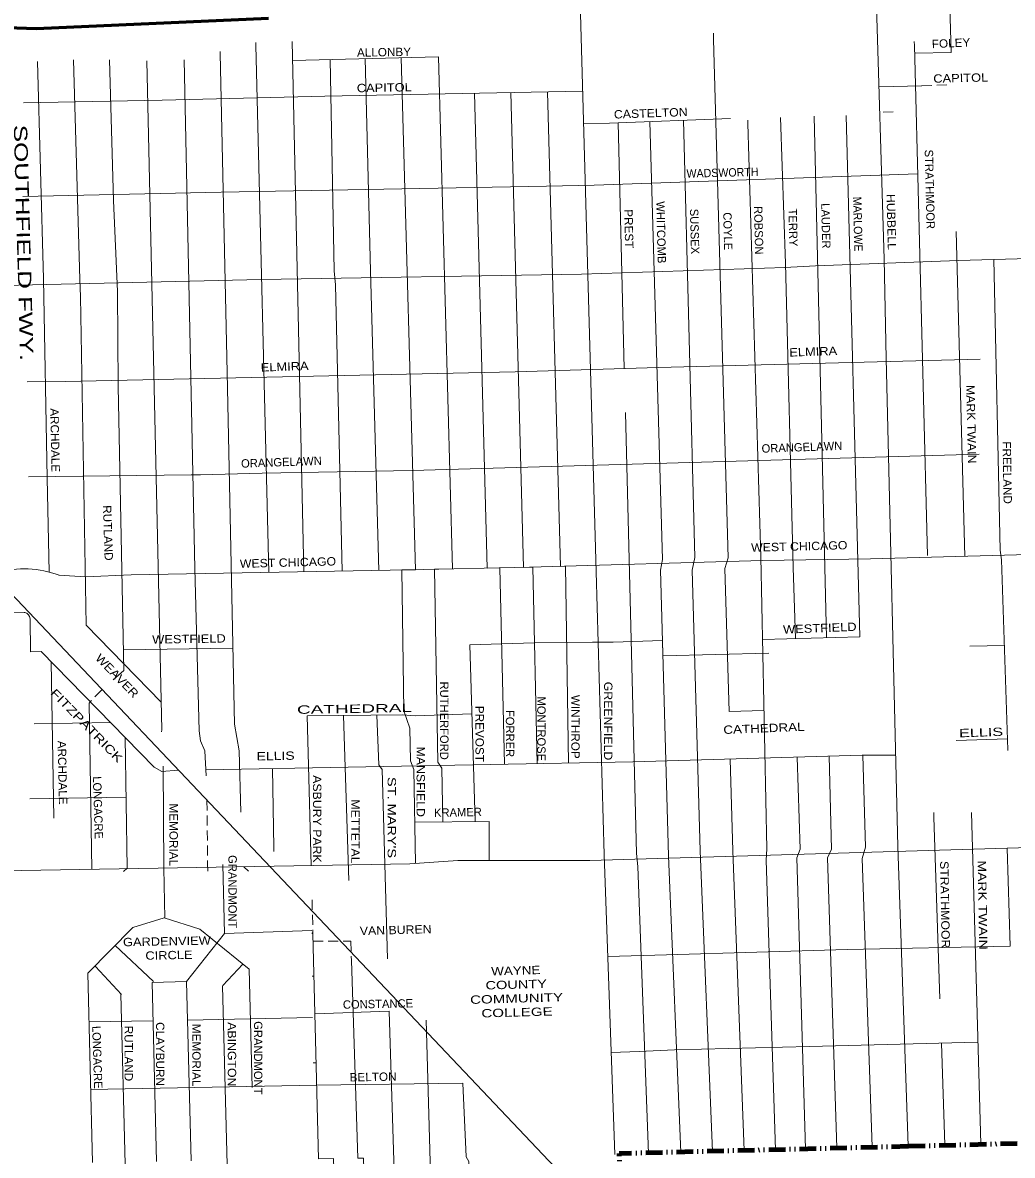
# Model space of a CAD drawing. Extents: x 34705 to 138605, y 34275 to 143551.
# Drawn here: x 54154 to 63036, y 107069 to 117233 of the extents above; entities that cross this region are included whole.
import ezdxf
from ezdxf.enums import TextEntityAlignment as Align

# ---------------------------------------------------------------- set-up
doc = ezdxf.new("R2010")
doc.units = 0
doc.header["$LTSCALE"] = 30
doc.linetypes.add('DASH_DOUBLE_DOT', pattern=[9.2, 5, -1.2, 0.3, -1.2, 0.3, -1.2])
doc.linetypes.add('MEDIUM_DASHED', pattern=[4.5, 3, -1.5])
for name, color, linetype, lineweight in [('1', 7, 'Continuous', 13), ('11', 7, 'Continuous', 13), ('50', 7, 'Continuous', 13), ('51', 7, 'Continuous', 35), ('59', 7, 'DASH_DOUBLE_DOT', 106)]:
    doc.layers.add(name, color=color, linetype=linetype, lineweight=lineweight)

msp = doc.modelspace()

# ---------------------------------------------------------------- linework, layer by layer
at = {"layer": '1'}
for p, q in [((56571.12, 117064.72), (56678.04, 112305.29)), ((56574.95, 116894.51), (57885.23, 116925.82)), ((62159.2, 116960.26), (62486.23, 116964.8)), ((61839.17, 116656.14), (62221.01, 116667.06)), ((61257.31, 116394.83), (61367.08, 111713.13)), ((61544.82, 116401.03), (61667.13, 111721.32)), ((59497.55, 116333.43), (59553.16, 114128.11)), ((62531.88, 115360.4), (62608.33, 112441.56)), ((54219.61, 111884.54), (54223.08, 111586.9)), ((54723.7, 111825.17), (55396.56, 111135.87)), ((60793.32, 111697.48), (61667.13, 111721.32)), ((55057.41, 111605.74), (56039.65, 111621.22)), ((58167.28, 111651.19), (58216, 110063.17)), ((62653.95, 111636.51), (62964.87, 111644.49)), ((54410.01, 111496.33), (54432.83, 110095.19)), ((56707.13, 111013.72), (56742.82, 109668.54)), ((57033.71, 111016.67), (57080.65, 109536.08)), ((60493.36, 111051.96), (60806.77, 111060.21)), ((54257.41, 110941.34), (54943.75, 110952.62)), ((62530.97, 110790.77), (62992.76, 110806.7)), ((55414.35, 110559.67), (55419.78, 109646.04)), ((54217.06, 110268.58), (55082.01, 110283.75)), ((62668.48, 110145.25), (62752.45, 107173.38)), ((62990.46, 109823.82), (63016.12, 108946.83)), ((55419.78, 109646.04), (55430.79, 109197.62)), ((56139.63, 109658.28), (56179.96, 109620.23)), ((56748.25, 109066.01), (56758.48, 109054.95)), ((55625.31, 108628.52), (55966.16, 109059.65)), ((54982.97, 108951.23), (55326.76, 108628.52)), ((55041.15, 108511.98), (54806.4, 108764.37)), ((55950.51, 108591.62), (56129.68, 108785.34)), ((54738.37, 108703.06), (54780.11, 107003.63)), ((56186.99, 108738.64), (56213.07, 107676.57)), ((56752.67, 108676.4), (56767.76, 108676.9)), ((55314.79, 108620.9), (55625.31, 108628.52)), ((55314.79, 108620.9), (55354.27, 107013.34)), ((55625.31, 108628.52), (55664.85, 107018.6)), ((55948.62, 108589.57), (55988.06, 106983.62)), ((55035.71, 108514.29), (55073.16, 106989.62)), ((56776.09, 108337.51), (57442.56, 108361.32)), ((55323.23, 108276.96), (54749.11, 108265.68)), ((56754.28, 108305.07), (55633.79, 108283.06)), ((62399.37, 108076.46), (62429.56, 107163.12)), ((56761.51, 107898.92), (56786.85, 107898.92)), ((56791.74, 107699.78), (54763.91, 107659.95)), ((56791.74, 107699.78), (58104.66, 107715.6))]:
    msp.add_line(p, q, dxfattribs=at)
at = {"layer": '1', "linetype": 'MEDIUM_DASHED'}
for p, q in [((62223.51, 116667.13), (62449.23, 116673.58)), ((61876.25, 116428.56), (62002.29, 116433.23)), ((54863.92, 111247.18), (54760.58, 111138.57)), ((55807.35, 110253.12), (55813.82, 109652.74)), ((56750.95, 109361.84), (56758.48, 109055.1)), ((56760.04, 108991.66), (57097.93, 108991.66)), ((57097.93, 108991.66), (57103.55, 108817.23))]:
    msp.add_line(p, q, dxfattribs=at)
at = {"layer": '1'}
for points in [[(61799.97, 117893.3), (61810.66, 117579.32), (61886.86, 115111.82), (61904.86, 114220.52), (62009.46, 109840.12), (62100.56, 107154.18)], [(59156.14, 117419.97), (59299.97, 112306.17), (59371.51, 109768.6), (59467.9, 107076.6)], [(62469.74, 117407.16), (62474.36, 117381.92), (62486.23, 116964.8)], [(60353.03, 117137.36), (60354.23, 117080.61), (60484.66, 112430.42), (60454.76, 112334.62), (60493.36, 111051.96)], [(56246.14, 117054.36), (56246.96, 117032.18), (56363.82, 112299.47)], [(62153.89, 117064.56), (62157.46, 117029.02), (62273.03, 112452.52)], [(54610.21, 116897.96), (54666.34, 114928.14), (54671.96, 114776.22), (54723.7, 111825.17)], [(54934.03, 116899.27), (54970.07, 115635.68), (55003.82, 114819.84), (55009.44, 113970.24), (55061.16, 111420.92), (54965.56, 111337.12)], [(55602.17, 116899.09), (55698.47, 112335.75), (55737.84, 110878.49), (55748.86, 110789.82), (55788.46, 110698.44), (55799.71, 110473.38)], [(55925.96, 116973.09), (55926.76, 116957.22), (55988.13, 114094.02), (56053.86, 110939.32), (56095.66, 110700.02), (56112.01, 110148.89)], [(56912.74, 116902.58), (56949.95, 115006.91), (56961.26, 114881.52), (57022.26, 112311.67)], [(57228.43, 116910.12), (57276.18, 115006.91), (57351.47, 112317.77)], [(57550.14, 116917.81), (57678.31, 112323.99), (57555.44, 112321.55), (57575.66, 111059.02), (57629.46, 110903.42), (57635.46, 110610.32), (57665.36, 110532.52), (57680.06, 109687.26)], [(57885.23, 116925.82), (58012.13, 112331.09), (57849.82, 112327.64), (57880.56, 110598.32), (57916.46, 110544.52), (57925.88, 110060.6)], [(54285.96, 116885.59), (54340.11, 114933.77), (54373.56, 113146.72), (54390.97, 112303.04)], [(55268.67, 116889.83), (55402.06, 110888.52), (55400.61, 110869.71)], [(54160.99, 116513.49), (55404.58, 116538.88), (56864.11, 116573.64), (59180.33, 116617.67)], [(58208.68, 116599.2), (58321.61, 112337.68), (58436.71, 112340.13), (58477.37, 110577.69)], [(58535.01, 116605.4), (58649.32, 112344.65), (58731.14, 112346.63), (58770.49, 110583)], [(58863.83, 116611.65), (58980.39, 112353.96), (59024.39, 112355.25), (59051.37, 110588.09)], [(60955.56, 116382.92), (61001.1, 115071.62), (61068.6, 112342.78), (61088.69, 111705.53)], [(59189.13, 116325.6), (59419.39, 116330.3), (60505.35, 116373.76)], [(59781.66, 116344.8), (59895.66, 112415.42), (59877.76, 112319.72), (59949.56, 109757.82), (60061.8, 107094.1)], [(60085.12, 116356.94), (60185.66, 112433.42), (60161.76, 112319.72), (60235.06, 109801.22), (60343.66, 107102.41)], [(60662.69, 116359.02), (60662.56, 116329.12), (60777.66, 112439.32), (60832.96, 109819.22), (60827.06, 109717.52), (60910.83, 107119.12)], [(54153.92, 115673.69), (55934.44, 115713.34), (58855.13, 115767.16), (59284.18, 115774.93), (62186.58, 115875.92)], [(40613.4, 114632.16), (42489.2, 114668.24), (47370.61, 114750.8), (48708.52, 114746.45), (48856.21, 114755.14), (56295.69, 114929.11), (59170.26, 114975.24), (60993.76, 115036.75), (61270.46, 115052.13), (62554.03, 115098.26), (64448.63, 115152.08), (64617.72, 115144.39), (66562.29, 115190.52), (67177.17, 115213.59), (67584.53, 115228.96), (71855.3, 115368.15)], [(62869.23, 115107.21), (62927.36, 112497.82), (62939.26, 112414.02), (62996.06, 110707.52), (62996.02, 110701.52)], [(54193.27, 114008.47), (54535.58, 114014.17), (58572.66, 114098.75), (59856.23, 114137.19), (62746.18, 114214.08)], [(59563.09, 113734.35), (59662.46, 109775.82), (59674.46, 109662.12), (59769.76, 107085.5)], [(54206.39, 113155.96), (55665.43, 113176.13), (55749.98, 113176.13), (56303.37, 113191.5), (57648.43, 113214.57), (62738.49, 113360.65)], [(54478.94, 112274.29), (54716.56, 112260.76), (55127.41, 112276.57), (57617.68, 112322.7), (58701.41, 112345.76), (60793.93, 112407.27), (61762.37, 112422.65), (68207.1, 112599.49), (70854.93, 112668.68), (71769.57, 112676.37), (72161.56, 112699.44), (75134.56, 112784.19)], [(53834.93, 111923.31), (53892.56, 111935.02), (54172.09, 111939.12)], [(58167.28, 111651.19), (58745.61, 111667.26), (59268.26, 111674.95), (59452.72, 111674.95), (59895.43, 111689.19), (59899.28, 111551.75), (60851.58, 111575)], [(54223.08, 111586.9), (54319.46, 111588.73), (55334.93, 110552.43), (55404.11, 110513.98), (55548.36, 110526.01)], [(54760.58, 111138.57), (54750.26, 111127.72), (54774.53, 109635.01)], [(56707.13, 111013.72), (57561.96, 111021.43), (57677.25, 111013.74), (58186.35, 111029.65)], [(57333.37, 111019.37), (57351.36, 110574.42), (57381.26, 110532.52), (57429.15, 108833.47)], [(55074.41, 110818.95), (55091.06, 109645.72), (55059.18, 109616.27)], [(55796.92, 110529.13), (59629.5, 110598.56), (61689.36, 110660.07), (61989.87, 110660.48)], [(60504.57, 110624.69), (60528.06, 109801.22), (60630.28, 107110.85)], [(61105.45, 110642.63), (61130.46, 109816.22), (61100.56, 109738.42), (61180.23, 107127.06)], [(61391.98, 110651.19), (61411.56, 109816.22), (61375.66, 109738.42), (61461.18, 107135.34)], [(61694.87, 110660.07), (61716.46, 109834.12), (61686.56, 109732.42), (61777.56, 107144.66)], [(56394.61, 110539.96), (56406.56, 109831.12), (56409.19, 109796.15)], [(62331.3, 110145.35), (62332.36, 110103.32), (62386.23, 108473.77)], [(40755.85, 109370.6), (41156.14, 109376.08), (42170.69, 109391.46), (42339.79, 109406.84), (42555, 109452.97), (42654.91, 109483.72), (42808.63, 109506.79), (42946.98, 109514.48), (43077.65, 109499.1), (43215.99, 109468.34), (43369.71, 109422.21), (43531.12, 109414.52), (43700.21, 109422.21), (48173.49, 109522.16), (55369.51, 109645.18), (57629.21, 109683.62), (58059.62, 109714.38), (59243.27, 109714.38), (63191.97, 109829.71), (66639.15, 109914.28), (68637.52, 109960.41), (71243.21, 110034.61)], [(57673.6, 110058.37), (58340.9, 110064.28), (58340.61, 109714.38)], [(55950.94, 109679.65), (55966.16, 109059.65), (56749.37, 109087.63)], [(55814.42, 109652.75), (55814.66, 109632.22), (55814.66, 109618.94)], [(54738.37, 108703.06), (55142.6, 109113.61), (55424.7, 109199.53), (55744.8, 109098.97), (56186.99, 108738.64)], [(56758.49, 109054.95), (56808.02, 107037.96), (56944.05, 107040.26), (57029.13, 104394.12), (56883.31, 104391.5), (56950.86, 101784.23)], [(59404.3, 108852.85), (59933.09, 108868.64), (61554.84, 108914.77), (63016.12, 108946.83)], [(57103.55, 108817.23), (57160.72, 107043.93), (57212.55, 107044.8), (57293.42, 104398.87), (57236.89, 104397.85), (57309.89, 101788.29)], [(57442.56, 108361.32), (57608.46, 103092.22), (57638.41, 101792)], [(57775.96, 108281.72), (57835.76, 106162.62), (57900.52, 104474.17), (57937.36, 103110.22), (57973.38, 101795.79)], [(59435.12, 107991.96), (59687.14, 107999.83), (60002.27, 108015.21), (61216.66, 108045.97), (62726.7, 108084.9)], [(58104.66, 107715.6), (58134.66, 107055.42), (58158.66, 107013.52), (58314.79, 101799.65)]]:
    msp.add_lwpolyline(points, dxfattribs=at)
for centre, radius, start, end in [((54168.04, 111463.65), 868.49, 68.96068, 106.22392), ((54172.01, 111888.66), 50.46, 89.91597, 94.47871), ((54162.51, 111882.8), 57.12, 1.75211, 80.35073)]:
    msp.add_arc(centre, radius, start, end, dxfattribs=at)
at = {"layer": '50'}
msp.add_line((59512.68, 106348.96), (49626.02, 116766.15), dxfattribs=at)
at = {"layer": '51', "lineweight": 60}
msp.add_lwpolyline([(48854.63, 117669.11), (49514.91, 117195.42), (49843.37, 117046.99), (50290.23, 116966.93), (50990.53, 116953.58), (51340.96, 116954.17), (52322.56, 117053.7), (53651.68, 117200.44), (54278.61, 117180.42), (56361.16, 117273.82)], dxfattribs=at)
at = {"layer": '59'}
for p, q in [((62102.57, 107149.74), (59507.74, 107085.4)), ((62102.47, 107149.64), (64732.95, 107219.29))]:
    msp.add_line(p, q, dxfattribs=at)
msp.add_lwpolyline([(56980.51, 101772.19), (56980.51, 101772.19), (59657.77, 101818.91), (59507.74, 107085.4)], dxfattribs=at)

# ---------------------------------------------------------------- texts
at = {"layer": '11'}
for s, height, rotation, width, p in [('FOLEY', 75, 2.748, 1.05, (62487.37, 117011.83)), ('ALLONBY', 75, 0.879, 1.05, (57397.06, 116930.99)), ('CAPITOL', 75, 1.071, 1.15, (57399.72, 116612.85)), ('CAPITOL', 75, 1.373, 1.15, (62573.91, 116699.25)), ('CASTELTON', 75, 2, 1.1, (59791.83, 116383.53)), ('SOUTHFIELD FWY.', 120, 271.584, 1.45, (54102.7, 115255.21)), ('WADSWORTH', 75, 1.389, 0.95, (60435.15, 115849.71)), ('HUBBELL', 75, 271.388, 1.1, (61912.81, 115443.81)), ('MARLOWE', 75, 271.391, 0.95, (61611.93, 115424.41)), ('PREST', 75, 271.39, 1.05, (59556.85, 115382.04)), ('ELMIRA', 75, 2.069, 1.15, (61249.93, 114243.72)), ('ELMIRA', 75, 2.069, 1.15, (56506.19, 114109.32)), ('MARK TWAIN', 75, 271.372, 1.1, (62629.92, 113628.83)), ('ARCHDALE', 75, 271.201, 1.05, (54406.88, 113485.44)), ('FREELAND', 75, 271.002, 1.05, (62952.74, 113194.81)), ('RUTLAND', 75, 271.854, 1.05, (54881.75, 112653.12)), ('WEST CHICAGO', 75, 1.498, 1.1, (61124.29, 112496.18)), ('WEST CHICAGO', 75, 1.498, 1.1, (56535.57, 112351.44)), ('WESTFIELD', 75, 2.267, 1.15, (61309.31, 111762.55)), ('WESTFIELD', 75, 0.945, 1.15, (55646.91, 111665.4)), ('WEAVER', 75, 314.272, 1.15, (54974.23, 111345.57)), ('GREENFIELD', 75, 270, 1.1, (59371.63, 110966.06)), ('FITZPATRICK', 75, 314.299, 1.35, (54702.1, 110899.44)), ('WINTHROP', 75, 270, 1.05, (59077.81, 110914.25)), ('CATHEDRAL', 75, 0.975, 1.7, (57132.62, 111038.97)), ('PREVOST', 75, 270, 1.05, (58217.76, 110850.63)), ('CATHEDRAL ', 75, 2.268, 1.2, (60824.46, 110864.4)), ('ELLIS   ', 75, 2.001, 1.45, (62816.73, 110828.56)), ('ARCHDALE', 75, 271.201, 1.05, (54473.42, 110502.1)), ('ELLIS', 75, 1.211, 1.25, (56424.8, 110615.2)), ('MANSFIELD', 75, 270, 1.1, (57688.9, 110420.99)), ('ASBURY PARK', 75, 270, 1.1, (56759.39, 110087.54)), ("ST. MARY'S", 75, 270, 1.3, (57429.28, 110100.36)), ('MEMORIAL', 75, 270, 1.05, (55471.39, 109945.21)), ('METTETAL', 75, 270, 1.1, (57102.35, 109975.32)), ('STRATHMOOR ', 75, 271, 1.1, (62394.64, 109301.71)), ('MARK TWAIN ', 75, 271.001, 1.25, (62731.82, 109296.46)), ('VAN BUREN', 75, 1.58, 1.1, (57502.5, 109053.59)), ('GARDENVIEW ', 75, 1.14, 1.15, (55464.86, 108952.54)), ('CIRCLE', 75, 1.14, 1.15, (55467.35, 108827.56)), ('WAYNE', 75, 1.665, 1.2, (58580.42, 108689.24)), ('COUNTY', 75, 1.665, 1.3, (58584.05, 108564.29)), ('COMMUNITY', 75, 1.665, 1.35, (58587.68, 108439.34)), ('COLLEGE', 75, 1.665, 1.35, (58591.31, 108314.4)), ('CLAYBURN', 75, 270, 1.05, (55350.39, 107977.71)), ('ABINGTON', 75, 270, 1.1, (55994.82, 107975.22)), ('RUTLAND', 75, 270, 1.05, (55068.08, 107982.83)), ('MEMORIAL', 75, 270, 1.05, (55676.2, 107967.9)), ('BELTON', 75, 1.056, 1.05, (57299.1, 107735.21))]:
    msp.add_text(s, height=height, rotation=rotation, dxfattribs=dict(at, width=width)).set_placement(p, align=Align.CENTER)
for s, rotation, p in [('STRATHMOOR', 271.372, (62257.46, 115736.51)), ('WHITCOMB', 271.39, (59846.43, 115350.37)), ('ROBSON', 271.389, (60722.32, 115369.38)), ('LAUDER', 271.39, (61324.69, 115408.68)), ('SUSSEX', 271.39, (60147.26, 115358.69)), ('COYLE', 271.386, (60445, 115360.53)), ('TERRY', 271.39, (61030.48, 115393.7)), ('ORANGELAWN', 2.069, (61148.6, 113386.55)), ('ORANGELAWN', 2.069, (56477.21, 113252.15)), ('RUTHERFORD', 270, (57900.44, 110969.27)), ('MONTROSE', 270, (58771.95, 110896.07)), ('FORRER', 270, (58490.31, 110853.66)), ('LONGACRE', 271.856, (54792.42, 110187.74)), ('KRAMER', 0.968, (58060.46, 110109.42)), ('GRANDMONT', 270, (56000.28, 109434.12)), ('CONSTANCE', 1.14, (57342.99, 108390.07)), ('GRANDMONT', 270, (56230.09, 107943.62)), ('LONGACRE', 271.856, (54786.44, 107947.67))]:
    msp.add_text(s, height=75, rotation=rotation, dxfattribs=at).set_placement(p, align=Align.CENTER)

doc.saveas('drawing.dxf')
